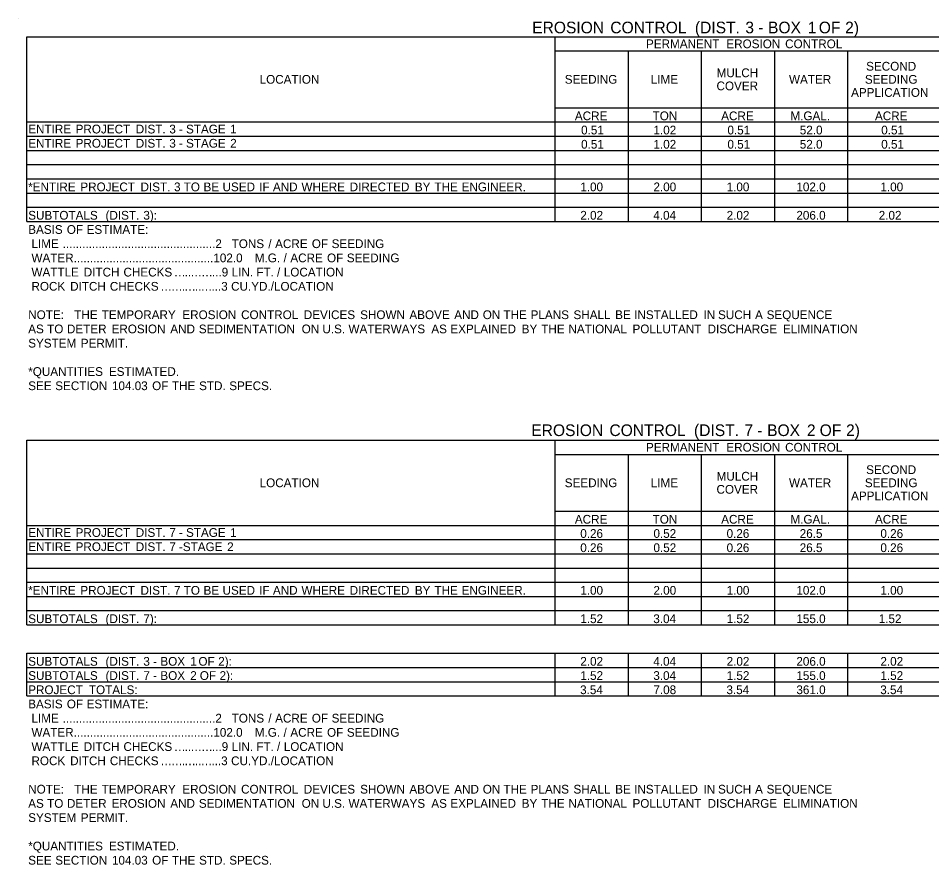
# Model space of a CAD drawing. Extents: x 544478 to 1930787, y -1948294 to 596640.
# Drawn here: x 544520 to 545147, y -1948049 to -1947468 of the extents above; entities that cross this region are included whole.
import ezdxf

# ---------------------------------------------------------------- set-up
doc = ezdxf.new("R2010")
doc.units = 0
doc.layers.add('Default', color=7, linetype='Continuous')

msp = doc.modelspace()

# ---------------------------------------------------------------- linework, layer by layer
at = {"layer": 'Default'}
for p, q in [((544519.98, -1947468.16), (544519.98, -1947468.16)), ((544525.83, -1947480.84), (545443.79, -1947480.84)), ((544525.83, -1947607.59), (544525.83, -1947480.84)), ((544525.83, -1947607.59), (544525.83, -1947480.84)), ((544888.53, -1947607.59), (544888.53, -1947480.84)), ((544888.53, -1947490.59), (545443.79, -1947490.59)), ((544938.74, -1947607.59), (544938.74, -1947490.59)), ((544988.95, -1947607.59), (544988.95, -1947490.59)), ((545039.17, -1947607.59), (545039.17, -1947490.59)), ((545089.38, -1947607.59), (545089.38, -1947490.59)), ((544888.53, -1947529.59), (545383.83, -1947529.59)), ((544938.74, -1947607.59), (544938.74, -1947529.59)), ((544988.95, -1947597.84), (544988.95, -1947529.59)), ((545039.17, -1947597.84), (545039.17, -1947529.59)), ((545089.38, -1947597.84), (545089.38, -1947529.59)), ((544525.83, -1947539.34), (545443.79, -1947539.34)), ((544525.83, -1947549.09), (545443.79, -1947549.09)), ((544525.83, -1947558.84), (545443.79, -1947558.84)), ((544525.83, -1947568.59), (545443.79, -1947568.59)), ((544525.83, -1947578.34), (545443.79, -1947578.34)), ((544525.83, -1947588.09), (545443.79, -1947588.09)), ((544525.83, -1947597.84), (545272.19, -1947597.84)), ((544888.53, -1947607.59), (544888.53, -1947597.84)), ((544938.74, -1947597.84), (545149.83, -1947597.84)), ((544525.83, -1947607.59), (545443.79, -1947607.59)), ((544525.83, -1947757.74), (545443.79, -1947757.74)), ((544525.83, -1947884.49), (544525.83, -1947757.74)), ((544525.83, -1947884.49), (544525.83, -1947757.74)), ((544888.53, -1947884.49), (544888.53, -1947757.74)), ((544888.53, -1947767.49), (545443.79, -1947767.49)), ((544938.74, -1947884.49), (544938.74, -1947767.49)), ((544988.95, -1947884.49), (544988.95, -1947767.49)), ((545039.17, -1947884.49), (545039.17, -1947767.49)), ((545089.38, -1947884.49), (545089.38, -1947767.49)), ((544888.53, -1947806.49), (545383.83, -1947806.49)), ((544938.74, -1947884.49), (544938.74, -1947806.49)), ((544988.95, -1947874.74), (544988.95, -1947806.49)), ((545039.17, -1947874.74), (545039.17, -1947806.49)), ((545089.38, -1947874.74), (545089.38, -1947806.49)), ((544525.83, -1947816.24), (545443.79, -1947816.24)), ((544525.83, -1947825.99), (545443.79, -1947825.99)), ((544525.83, -1947835.74), (545443.79, -1947835.74)), ((544525.83, -1947845.49), (545443.79, -1947845.49)), ((544525.83, -1947855.24), (545443.79, -1947855.24)), ((544525.83, -1947864.99), (545443.79, -1947864.99)), ((544525.83, -1947874.74), (545272.19, -1947874.74)), ((544888.53, -1947884.49), (544888.53, -1947874.74)), ((544938.74, -1947874.74), (545149.83, -1947874.74)), ((544525.83, -1947884.49), (545443.79, -1947884.49)), ((544525.83, -1947903.99), (545443.79, -1947903.99)), ((544525.83, -1947903.99), (545443.79, -1947903.99)), ((544525.83, -1947933.24), (544525.83, -1947903.99)), ((544525.83, -1947933.24), (544525.83, -1947903.99)), ((544888.53, -1947933.24), (544888.53, -1947903.99)), ((544888.53, -1947933.24), (544888.53, -1947903.99)), ((544938.74, -1947933.24), (544938.74, -1947903.99)), ((544988.95, -1947933.24), (544988.95, -1947903.99)), ((545039.17, -1947933.24), (545039.17, -1947903.99)), ((545089.38, -1947933.24), (545089.38, -1947903.99)), ((544525.83, -1947913.74), (545443.79, -1947913.74)), ((544938.74, -1947933.24), (544938.74, -1947913.74)), ((544988.95, -1947933.24), (544988.95, -1947913.74)), ((545039.17, -1947933.24), (545039.17, -1947913.74)), ((545089.38, -1947933.24), (545089.38, -1947913.74)), ((544525.83, -1947923.49), (545443.79, -1947923.49)), ((544525.83, -1947933.24), (545443.79, -1947933.24))]:
    msp.add_line(p, q, dxfattribs=at)

# ---------------------------------------------------------------- texts
for s, height, p in [('EROSION', 8, (544872.67, -1947478.5)), (' CONTROL', 8, (544923.32, -1947478.5)), (' (DIST.', 8, (544981.36, -1947478.5)), (' 3', 8, (545015.98, -1947478.5)), (' BOX', 8, (545031.56, -1947478.5)), (' 1', 8, (545058.88, -1947478.5)), (' OF', 8, (545066.39, -1947478.5)), (' 2)', 8, (545084.49, -1947478.5)), (' -', 8, (545024.82, -1947478.5)), ('PERMANENT', 6, (544950.79, -1947488.71)), (' EROSION', 6, (545003.72, -1947488.71)), (' CONTROL', 6, (545044.04, -1947488.71)), ('MULCH', 6, (544999.25, -1947508.59)), ('SECOND', 6, (545101.87, -1947504.09)), ('LOCATION', 6, (544685.62, -1947513.09)), ('SEEDING', 6, (544895.02, -1947513.09)), ('LIME', 6, (544954.04, -1947513.09)), ('WATER', 6, (545048.92, -1947513.09)), ('SEEDING', 6, (545100.99, -1947513.09)), ('COVER', 6, (544999.17, -1947517.59)), ('APPLICATION', 6, (545091.53, -1947522.09)), ('ACRE', 6, (544901.96, -1947538.14)), ('TON', 6, (544955.33, -1947538.14)), ('ACRE', 6, (545002.39, -1947538.14)), ('M.GAL.', 6, (545049.89, -1947538.14)), ('ACRE', 6, (545107.93, -1947538.14)), ('ENTIRE', 6, (544526.8, -1947547.21)), (' PROJECT', 6, (544557.1, -1947547.21)), (' DIST.', 6, (544598.39, -1947547.21)), (' 3', 6, (544621.41, -1947547.21)), (' STAGE', 6, (544632.88, -1947547.21)), (' 1', 6, (544663.18, -1947547.21)), (' -', 6, (544628.02, -1947547.21)), ('0.51', 6, (544906.25, -1947547.89)), ('1.02', 6, (544955.91, -1947547.89)), ('0.51', 6, (545006.68, -1947547.89)), ('52.0', 6, (545056.32, -1947547.89)), ('0.51', 6, (545112.22, -1947547.89)), ('ENTIRE', 6, (544526.8, -1947556.96)), (' PROJECT', 6, (544557.1, -1947556.96)), (' DIST.', 6, (544598.39, -1947556.96)), (' 3', 6, (544621.41, -1947556.96)), (' STAGE', 6, (544632.88, -1947556.96)), (' 2', 6, (544663.18, -1947556.96)), ('0.51', 6, (544906.25, -1947557.64)), ('1.02', 6, (544955.91, -1947557.64)), ('0.51', 6, (545006.68, -1947557.64)), ('52.0', 6, (545056.32, -1947557.64)), ('0.51', 6, (545112.22, -1947557.64)), (' -', 6, (544628.02, -1947556.96)), ('*ENTIRE', 6, (544526.8, -1947586.89)), (' PROJECT', 6, (544560.36, -1947586.89)), (' DIST.', 6, (544601.65, -1947586.89)), (' 3', 6, (544624.67, -1947586.89)), (' TO', 6, (544631.28, -1947586.89)), (' BE', 6, (544644.88, -1947586.89)), (' USED', 6, (544657.94, -1947586.89)), (' IF', 6, (544683.12, -1947586.89)), (' AND', 6, (544692.51, -1947586.89)), (' WHERE', 6, (544712.09, -1947586.89)), (' DIRECTED', 6, (544745.18, -1947586.89)), (' BY', 6, (544789.92, -1947586.89)), (' THE', 6, (544803.37, -1947586.89)), (' ENGINEER.', 6, (544822.01, -1947586.89)), ('1.00', 6, (544905.68, -1947586.89)), ('2.00', 6, (544955.89, -1947586.89)), ('1.00', 6, (545006.11, -1947586.89)), ('102.0', 6, (545053.99, -1947586.89)), ('1.00', 6, (545111.65, -1947586.89)), ('SUBTOTALS', 6, (544526.8, -1947606.39)), (' (DIST.', 6, (544577.63, -1947606.39)), (' 3):', 6, (544603.6, -1947606.39)), ('2.02', 6, (544905.69, -1947606.39)), ('4.04', 6, (544955.79, -1947606.39)), ('2.02', 6, (545006.12, -1947606.39)), ('206.0', 6, (545053.99, -1947606.39)), ('2.02', 6, (545110.5, -1947606.39)), ('BASIS', 6, (544526.8, -1947616.14)), (' OF', 6, (544551.06, -1947616.14)), (' ESTIMATE:', 6, (544564.65, -1947616.14)), (' LIME', 6, (544526.8, -1947625.89)), (' ...............................................2', 6, (544548.25, -1947625.89)), (' TONS', 6, (544664.19, -1947625.89)), (' /', 6, (544689.37, -1947625.89)), (' ACRE', 6, (544694.03, -1947625.89)), (' OF', 6, (544719.21, -1947625.89)), (' SEEDING', 6, (544732.8, -1947625.89)), (' WATER...........................................102.0', 6, (544526.8, -1947635.64)), (' M.G.', 6, (544680.06, -1947635.64)), (' /', 6, (544699.82, -1947635.64)), (' ACRE', 6, (544704.48, -1947635.64)), (' OF', 6, (544729.65, -1947635.64)), (' SEEDING', 6, (544743.24, -1947635.64)), (' WATTLE', 6, (544526.8, -1947645.39)), (' DITCH', 6, (544562.68, -1947645.39)), (' CHECKS', 6, (544589.95, -1947645.39)), ('...9', 6, (544652.9, -1947645.39)), (' LIN.', 6, (544664.18, -1947645.39)), (' FT.', 6, (544681.14, -1947645.39)), (' /', 6, (544695.31, -1947645.39)), (' LOCATION', 6, (544699.97, -1947645.39)), ('…', 6, (544626.78, -1947645.39)), ('..', 6, (544634.18, -1947645.39)), ('…', 6, (544638.1, -1947645.39)), ('…', 6, (544645.5, -1947645.39)), (' ROCK', 6, (544526.8, -1947655.14)), (' DITCH', 6, (544553.34, -1947655.14)), (' CHECKS', 6, (544580.6, -1947655.14)), ('...3', 6, (544652.55, -1947655.14)), (' CU.YD./LOCATION', 6, (544663.81, -1947655.14)), ('…', 6, (544617.43, -1947655.14)), ('…', 6, (544624.83, -1947655.14)), ('.', 6, (544632.23, -1947655.14)), ('…', 6, (544633.83, -1947655.14)), ('..', 6, (544641.23, -1947655.14)), ('…', 6, (544645.15, -1947655.14)), ('NOTE:', 6, (544526.8, -1947674.64)), ('   THE', 6, (544551.69, -1947674.64)), (' TEMPORARY', 6, (544574.99, -1947674.64)), (' EROSION', 6, (544630.37, -1947674.64)), (' CONTROL', 6, (544670.67, -1947674.64)), (' DEVICES', 6, (544713.69, -1947674.64)), (' SHOWN', 6, (544752.39, -1947674.64)), (' ABOVE', 6, (544786.17, -1947674.64)), (' AND', 6, (544816.94, -1947674.64)), (' ON', 6, (544836.53, -1947674.64)), (' THE', 6, (544850.74, -1947674.64)), (' PLANS', 6, (544869.39, -1947674.64)), (' SHALL', 6, (544898.78, -1947674.64)), (' BE', 6, (544927.37, -1947674.64)), (' INSTALLED', 6, (544940.43, -1947674.64)), (' IN', 6, (544987.97, -1947674.64)), (' SUCH', 6, (544997.99, -1947674.64)), (' A', 6, (545023.4, -1947674.64)), (' SEQUENCE', 6, (545031.34, -1947674.64)), ('AS', 6, (544526.8, -1947684.39)), (' TO', 6, (544537.55, -1947684.39)), (' DETER', 6, (544551.15, -1947684.39)), (' EROSION', 6, (544581.78, -1947684.39)), (' AND', 6, (544622.08, -1947684.39)), (' SEDIMENTATION', 6, (544641.67, -1947684.39)), (' ON', 6, (544712.25, -1947684.39)), (' U.S.', 6, (544726.47, -1947684.39)), (' WATERWAYS', 6, (544744.37, -1947684.39)), (' AS', 6, (544801.22, -1947684.39)), (' EXPLAINED', 6, (544814.29, -1947684.39)), (' BY', 6, (544863.24, -1947684.39)), (' THE', 6, (544876.69, -1947684.39)), (' NATIONAL', 6, (544895.34, -1947684.39)), (' POLLUTANT', 6, (544939.29, -1947684.39)), (' DISCHARGE', 6, (544990.83, -1947684.39)), (' ELIMINATION', 6, (545042.56, -1947684.39)), ('SYSTEM', 6, (544526.8, -1947694.14)), (' PERMIT.', 6, (544560.65, -1947694.14)), ('*QUANTITIES', 6, (544526.8, -1947713.64)), (' ESTIMATED.', 6, (544579.93, -1947713.64)), ('SEE', 6, (544526.8, -1947723.39)), (' SECTION', 6, (544543.13, -1947723.39)), (' 104.03', 6, (544582.04, -1947723.39)), (' OF', 6, (544609.62, -1947723.39)), (' THE', 6, (544623.21, -1947723.39)), (' STD.', 6, (544641.85, -1947723.39)), (' SPECS.', 6, (544662.55, -1947723.39)), ('EROSION', 8, (544872.05, -1947754.91)), (' CONTROL', 8, (544922.71, -1947754.91)), (' (DIST.', 8, (544980.74, -1947754.91)), (' 7', 8, (545015.36, -1947754.91)), (' BOX', 8, (545030.93, -1947754.91)), (' 2', 8, (545058.25, -1947754.91)), (' OF', 8, (545067, -1947754.91)), (' 2)', 8, (545085.11, -1947754.91)), (' -', 8, (545024.19, -1947754.91)), ('PERMANENT', 6, (544950.79, -1947765.61)), (' EROSION', 6, (545003.72, -1947765.61)), (' CONTROL', 6, (545044.04, -1947765.61)), ('MULCH', 6, (544999.25, -1947785.49)), ('SECOND', 6, (545101.87, -1947780.99)), ('LOCATION', 6, (544685.62, -1947789.99)), ('SEEDING', 6, (544895.02, -1947789.99)), ('LIME', 6, (544954.04, -1947789.99)), ('WATER', 6, (545048.92, -1947789.99)), ('SEEDING', 6, (545100.99, -1947789.99)), ('COVER', 6, (544999.17, -1947794.49)), ('APPLICATION', 6, (545091.53, -1947798.99)), ('ACRE', 6, (544901.96, -1947815.04)), ('TON', 6, (544955.33, -1947815.04)), ('ACRE', 6, (545002.39, -1947815.04)), ('M.GAL.', 6, (545049.89, -1947815.04)), ('ACRE', 6, (545107.93, -1947815.04)), ('ENTIRE', 6, (544526.8, -1947824.11)), (' PROJECT', 6, (544557.1, -1947824.11)), (' DIST.', 6, (544598.39, -1947824.11)), (' 7', 6, (544621.41, -1947824.11)), (' -', 6, (544628.02, -1947824.11)), (' STAGE', 6, (544632.88, -1947824.11)), (' 1', 6, (544663.18, -1947824.11)), ('0.26', 6, (544905.67, -1947824.79)), ('0.52', 6, (544955.91, -1947824.79)), ('0.26', 6, (545006.09, -1947824.79)), ('26.5', 6, (545056.28, -1947824.79)), ('0.26', 6, (545111.64, -1947824.79)), ('ENTIRE', 6, (544526.8, -1947833.86)), (' PROJECT', 6, (544557.1, -1947833.86)), (' DIST.', 6, (544598.39, -1947833.86)), (' 7', 6, (544621.41, -1947833.86)), (' -STAGE', 6, (544628.02, -1947833.86)), (' 2', 6, (544661.11, -1947833.86)), ('0.26', 6, (544905.67, -1947834.54)), ('0.52', 6, (544955.91, -1947834.54)), ('0.26', 6, (545006.09, -1947834.54)), ('26.5', 6, (545056.28, -1947834.54)), ('0.26', 6, (545111.64, -1947834.54)), ('*ENTIRE', 6, (544526.8, -1947863.79)), (' PROJECT', 6, (544560.36, -1947863.79)), (' DIST.', 6, (544601.65, -1947863.79)), (' 7', 6, (544624.67, -1947863.79)), (' TO', 6, (544631.28, -1947863.79)), (' BE', 6, (544644.88, -1947863.79)), (' USED', 6, (544657.94, -1947863.79)), (' IF', 6, (544683.12, -1947863.79)), (' AND', 6, (544692.51, -1947863.79)), (' WHERE', 6, (544712.09, -1947863.79)), (' DIRECTED', 6, (544745.18, -1947863.79)), (' BY', 6, (544789.92, -1947863.79)), (' THE', 6, (544803.37, -1947863.79)), (' ENGINEER.', 6, (544822.01, -1947863.79)), ('1.00', 6, (544905.68, -1947863.79)), ('2.00', 6, (544955.89, -1947863.79)), ('1.00', 6, (545006.11, -1947863.79)), ('102.0', 6, (545053.99, -1947863.79)), ('1.00', 6, (545111.65, -1947863.79)), ('SUBTOTALS', 6, (544526.8, -1947883.29)), (' (DIST.', 6, (544577.63, -1947883.29)), (' 7):', 6, (544603.6, -1947883.29)), ('1.52', 6, (544905.69, -1947883.29)), ('3.04', 6, (544955.79, -1947883.29)), ('1.52', 6, (545006.12, -1947883.29)), ('155.0', 6, (545053.99, -1947883.29)), ('1.52', 6, (545110.5, -1947883.29)), ('SUBTOTALS', 6, (544526.8, -1947912.54)), (' (DIST.', 6, (544577.63, -1947912.54)), (' 3', 6, (544603.6, -1947912.54)), (' -', 6, (544610.22, -1947912.54)), (' BOX', 6, (544615.28, -1947912.54)), (' 1', 6, (544635.77, -1947912.54)), (' OF', 6, (544641.4, -1947912.54)), (' 2):', 6, (544654.98, -1947912.54)), ('2.02', 6, (544905.69, -1947912.54)), ('4.04', 6, (544955.79, -1947912.54)), ('2.02', 6, (545006.12, -1947912.54)), ('206.0', 6, (545053.99, -1947912.54)), ('2.02', 6, (545111.66, -1947912.54)), ('SUBTOTALS', 6, (544526.8, -1947922.29)), (' (DIST.', 6, (544577.63, -1947922.29)), (' 7', 6, (544603.6, -1947922.29)), (' BOX', 6, (544615.27, -1947922.29)), (' 2', 6, (544635.76, -1947922.29)), (' OF', 6, (544642.33, -1947922.29)), (' 2):', 6, (544655.91, -1947922.29)), ('1.52', 6, (544905.69, -1947922.29)), ('3.04', 6, (544955.79, -1947922.29)), ('1.52', 6, (545006.12, -1947922.29)), ('155.0', 6, (545053.99, -1947922.29)), ('1.52', 6, (545111.66, -1947922.29)), (' -', 6, (544610.21, -1947922.29)), ('PROJECT', 6, (544526.8, -1947932.04)), (' TOTALS:', 6, (544566.23, -1947932.04)), ('3.54', 6, (544905.58, -1947932.04)), ('7.08', 6, (544955.88, -1947932.04)), ('3.54', 6, (545006, -1947932.04)), ('361.0', 6, (545053.99, -1947932.04)), ('3.54', 6, (545111.54, -1947932.04)), ('BASIS', 6, (544526.8, -1947941.79)), (' OF', 6, (544551.06, -1947941.79)), (' ESTIMATE:', 6, (544564.65, -1947941.79)), (' LIME', 6, (544526.8, -1947951.54)), (' ...............................................2', 6, (544548.25, -1947951.54)), (' TONS', 6, (544664.19, -1947951.54)), (' /', 6, (544689.37, -1947951.54)), (' ACRE', 6, (544694.03, -1947951.54)), (' OF', 6, (544719.21, -1947951.54)), (' SEEDING', 6, (544732.8, -1947951.54)), (' /', 6, (544699.82, -1947961.29)), (' WATER...........................................102.0', 6, (544526.8, -1947961.29)), (' M.G.', 6, (544680.06, -1947961.29)), (' ACRE', 6, (544704.48, -1947961.29)), (' OF', 6, (544729.65, -1947961.29)), (' SEEDING', 6, (544743.24, -1947961.29)), (' WATTLE', 6, (544526.8, -1947971.04)), (' DITCH', 6, (544562.68, -1947971.04)), (' CHECKS', 6, (544589.95, -1947971.04)), ('...9', 6, (544652.9, -1947971.04)), (' LIN.', 6, (544664.18, -1947971.04)), (' FT.', 6, (544681.14, -1947971.04)), (' /', 6, (544695.31, -1947971.04)), (' LOCATION', 6, (544699.97, -1947971.04)), ('…', 6, (544626.78, -1947971.04)), ('..', 6, (544634.18, -1947971.04)), ('…', 6, (544638.1, -1947971.04)), ('…', 6, (544645.5, -1947971.04)), (' ROCK', 6, (544526.8, -1947980.79)), (' DITCH', 6, (544553.34, -1947980.79)), (' CHECKS', 6, (544580.6, -1947980.79)), ('…', 6, (544617.43, -1947980.79)), ('…', 6, (544624.83, -1947980.79)), ('.', 6, (544632.23, -1947980.79)), ('…', 6, (544633.83, -1947980.79)), ('..', 6, (544641.23, -1947980.79)), ('…', 6, (544645.15, -1947980.79)), ('...3', 6, (544652.55, -1947980.79)), (' CU.YD./LOCATION', 6, (544663.81, -1947980.79)), ('NOTE:', 6, (544526.8, -1948000.29)), ('   THE', 6, (544551.69, -1948000.29)), (' TEMPORARY', 6, (544574.99, -1948000.29)), (' EROSION', 6, (544630.37, -1948000.29)), (' CONTROL', 6, (544670.67, -1948000.29)), (' DEVICES', 6, (544713.69, -1948000.29)), (' SHOWN', 6, (544752.39, -1948000.29)), (' ABOVE', 6, (544786.17, -1948000.29)), (' AND', 6, (544816.94, -1948000.29)), (' ON', 6, (544836.53, -1948000.29)), (' THE', 6, (544850.74, -1948000.29)), (' PLANS', 6, (544869.39, -1948000.29)), (' SHALL', 6, (544898.78, -1948000.29)), (' BE', 6, (544927.37, -1948000.29)), (' INSTALLED', 6, (544940.43, -1948000.29)), (' IN', 6, (544987.97, -1948000.29)), (' SUCH', 6, (544997.99, -1948000.29)), (' A', 6, (545023.4, -1948000.29)), (' SEQUENCE', 6, (545031.34, -1948000.29)), ('AS', 6, (544526.8, -1948010.04)), (' TO', 6, (544537.55, -1948010.04)), (' DETER', 6, (544551.15, -1948010.04)), (' EROSION', 6, (544581.78, -1948010.04)), (' AND', 6, (544622.08, -1948010.04)), (' SEDIMENTATION', 6, (544641.67, -1948010.04)), (' ON', 6, (544712.25, -1948010.04)), (' U.S.', 6, (544726.47, -1948010.04)), (' WATERWAYS', 6, (544744.37, -1948010.04)), (' AS', 6, (544801.22, -1948010.04)), (' EXPLAINED', 6, (544814.29, -1948010.04)), (' BY', 6, (544863.24, -1948010.04)), (' THE', 6, (544876.69, -1948010.04)), (' NATIONAL', 6, (544895.34, -1948010.04)), (' POLLUTANT', 6, (544939.29, -1948010.04)), (' DISCHARGE', 6, (544990.83, -1948010.04)), (' ELIMINATION', 6, (545042.56, -1948010.04)), ('SYSTEM', 6, (544526.8, -1948019.79)), (' PERMIT.', 6, (544560.65, -1948019.79)), ('*QUANTITIES', 6, (544526.8, -1948039.29)), (' ESTIMATED.', 6, (544579.93, -1948039.29)), ('SEE', 6, (544526.8, -1948049.04)), (' SECTION', 6, (544543.13, -1948049.04)), (' 104.03', 6, (544582.04, -1948049.04)), (' OF', 6, (544609.62, -1948049.04)), (' THE', 6, (544623.21, -1948049.04)), (' STD.', 6, (544641.85, -1948049.04)), (' SPECS.', 6, (544662.55, -1948049.04))]:
    msp.add_text(s, height=height, dxfattribs=at).set_placement(p)

doc.saveas('drawing.dxf')
